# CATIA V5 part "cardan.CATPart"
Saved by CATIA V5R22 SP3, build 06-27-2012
Part number: User Library-Universal Joint222_Universal Bearing222
Revision: ANY
Definition: UNKNOWN
Nomenclature: User Library-Universal Joint222_Universal Bearing222
Source: Unknown
Bounding box of the stored display mesh (mm): x -38.1 to 38.1, y -38.1 to 38.1, z -15.875 to 15.875
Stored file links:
  C:\Users\PARTST~1\AppData\Local\Temp\WF6552.tmp\User Library-Universal Joint222_Universal Bearing222.CATPart
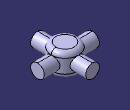
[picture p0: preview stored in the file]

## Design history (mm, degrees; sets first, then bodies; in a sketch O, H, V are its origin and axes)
Body1 "Fillet1" (main body)
  Solid1: solid without history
